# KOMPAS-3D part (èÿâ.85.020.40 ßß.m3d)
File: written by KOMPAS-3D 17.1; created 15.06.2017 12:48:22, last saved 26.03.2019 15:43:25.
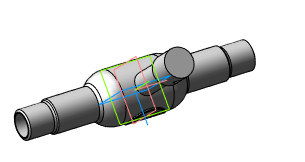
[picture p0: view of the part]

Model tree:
1. Операция без истории:2  (labels: Сталь 20  ГОСТ 1050-88)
